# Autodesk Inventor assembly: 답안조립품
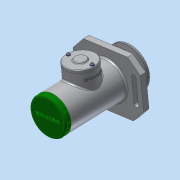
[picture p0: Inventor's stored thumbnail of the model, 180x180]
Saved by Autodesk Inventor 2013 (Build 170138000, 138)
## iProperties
Created: 2017-10
Part Number: 답안조립품
Document SubType Name: Assembly
Designer: dgall
Author: dgall
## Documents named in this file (20)
- C:\Users\dgall\Desktop\471007V1027\답안조립품.iam
- C:\Users\dgall\Desktop\471007V1027\본체.ipt
- C:\Users\dgall\Desktop\471007V1027\축.ipt
- C:\Users\dgall\Desktop\471007V1027\키 4 x 4 x 18.ipt
- C:\Users\dgall\Desktop\471007V1027\볼트 M4 x 10.ipt
- C:\Users\dgall\Desktop\471007V1027\와셔 4x16.ipt
- C:\Users\dgall\Desktop\471007V1027\V-벨트풀리.ipt
- C:\Users\dgall\Desktop\471007V1027\부시1.ipt
- C:\Users\dgall\Desktop\471007V1027\베어링 15 x 35 x 11.ipt
- C:\Users\dgall\Desktop\471007V1027\멈춤링 15 x 1.ipt
- C:\Users\dgall\Desktop\471007V1027\멈춤링 35x1.6.ipt
- C:\Users\dgall\Desktop\471007V1027\부시2.ipt
- C:\Users\dgall\Desktop\471007V1027\와셔 10x21.ipt
- C:\Users\dgall\Desktop\471007V1027\너트 M10.ipt
- C:\Users\dgall\Desktop\471007V1027\오일 실 15 25 7.ipt
- C:\Users\dgall\Desktop\471007V1027\탑 커버.ipt
- C:\Users\dgall\Desktop\471007V1027\십자볼트 M3 x 10.ipt
- C:\Users\dgall\Desktop\471007V1027\와셔 3x6.ipt
- C:\Users\dgall\Desktop\471007V1027\사이드 커버.ipt
- 사이드 커버.ipt
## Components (2 placed, 2 different names)
1. ISO 4017 M4 x 10:1
2. V-벨트풀리:1 — 각도:2
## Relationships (1: Angle 1)
- 각도:2 [Angle]: V-벨트풀리:1
